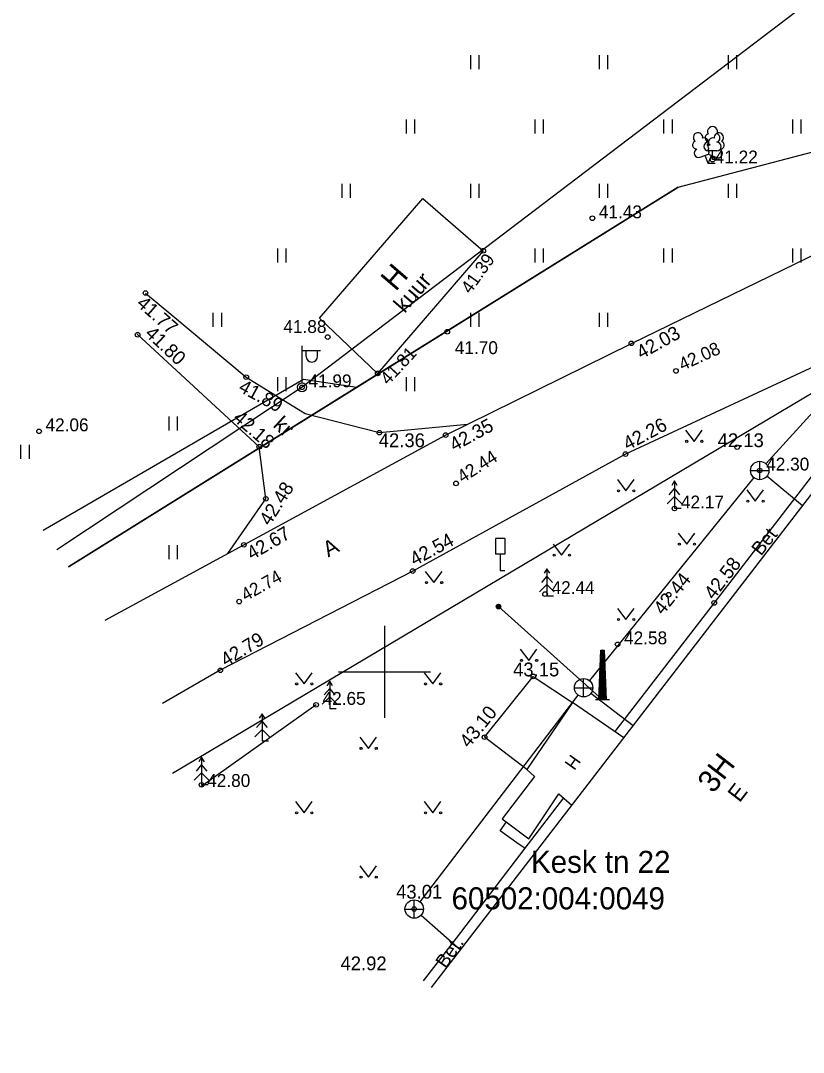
# Model space of a CAD drawing. Extents: x 641898 to 642452, y 6471715 to 6472255.
# Drawn here: x 641930.2 to 641972.8, y 6472029.3 to 6472085.4 of the extents above; entities that cross this region are included whole.
import ezdxf

# ---------------------------------------------------------------- set-up
doc = ezdxf.new("R2010")
doc.units = 0
for name, color, linetype in [('HALJASTUS', 7, 'Continuous'), ('HOONE', 7, 'Continuous'), ('HOONEDET', 7, 'Continuous'), ('KKAEV', 7, 'Continuous'), ('KORGUS-EH2000', 7, 'Continuous'), ('KTRASS', 7, 'Continuous'), ('LIIKLUS', 7, 'Continuous'), ('MPOHULIIN', 7, 'Continuous'), ('PIIR', 7, 'Continuous'), ('POST', 7, 'Continuous'), ('PUU', 7, 'Continuous'), ('RAJATIS', 7, 'Continuous'), ('TEE', 7, 'Continuous'), ('VORK', 7, 'Continuous')]:
    doc.layers.add(name, color=color, linetype=linetype)

msp = doc.modelspace()

# ---------------------------------------------------------------- linework, layer by layer
at = {"layer": 'HALJASTUS'}
for p, q in [((641954.672, 6472083.518), (641954.672, 6472082.757)), ((641955.127, 6472083.518), (641955.127, 6472082.757)), ((641961.672, 6472083.518), (641961.672, 6472082.757)), ((641962.127, 6472083.518), (641962.127, 6472082.757)), ((641968.672, 6472083.518), (641968.672, 6472082.757)), ((641969.127, 6472083.518), (641969.127, 6472082.757)), ((641951.172, 6472080.018), (641951.172, 6472079.257)), ((641951.627, 6472080.018), (641951.627, 6472079.257)), ((641958.172, 6472080.018), (641958.172, 6472079.257)), ((641958.627, 6472080.018), (641958.627, 6472079.257)), ((641965.172, 6472080.018), (641965.172, 6472079.257)), ((641965.627, 6472080.018), (641965.627, 6472079.257)), ((641972.172, 6472080.018), (641972.172, 6472079.257)), ((641972.627, 6472080.018), (641972.627, 6472079.257)), ((641947.672, 6472076.518), (641947.672, 6472075.757)), ((641948.127, 6472076.518), (641948.127, 6472075.757)), ((641954.672, 6472076.518), (641954.672, 6472075.757)), ((641955.127, 6472076.518), (641955.127, 6472075.757)), ((641961.672, 6472076.518), (641961.672, 6472075.757)), ((641962.127, 6472076.518), (641962.127, 6472075.757)), ((641968.672, 6472076.518), (641968.672, 6472075.757)), ((641969.127, 6472076.518), (641969.127, 6472075.757)), ((641944.172, 6472073.018), (641944.172, 6472072.257)), ((641944.627, 6472073.018), (641944.627, 6472072.257)), ((641958.172, 6472073.018), (641958.172, 6472072.257)), ((641958.627, 6472073.018), (641958.627, 6472072.257)), ((641965.172, 6472073.018), (641965.172, 6472072.257)), ((641965.627, 6472073.018), (641965.627, 6472072.257)), ((641972.172, 6472073.018), (641972.172, 6472072.257)), ((641972.627, 6472073.018), (641972.627, 6472072.257)), ((641940.672, 6472069.518), (641940.672, 6472068.757)), ((641941.127, 6472069.518), (641941.127, 6472068.757)), ((641954.672, 6472069.518), (641954.672, 6472068.757)), ((641955.127, 6472069.518), (641955.127, 6472068.757)), ((641961.672, 6472069.518), (641961.672, 6472068.757)), ((641962.127, 6472069.518), (641962.127, 6472068.757)), ((641944.172, 6472066.018), (641944.172, 6472065.257)), ((641944.627, 6472066.018), (641944.627, 6472065.257)), ((641951.172, 6472066.018), (641951.172, 6472065.257)), ((641951.627, 6472066.018), (641951.627, 6472065.257)), ((641938.272, 6472063.881), (641938.272, 6472063.119)), ((641938.728, 6472063.881), (641938.728, 6472063.119)), ((641966.362, 6472063.136), (641966.826, 6472062.529)), ((641966.826, 6472062.529), (641967.271, 6472063.136)), ((641930.214, 6472062.337), (641930.214, 6472061.576)), ((641930.669, 6472062.337), (641930.669, 6472061.576)), ((641962.658, 6472060.448), (641963.121, 6472059.841)), ((641963.121, 6472059.841), (641963.567, 6472060.448)), ((641969.69, 6472059.885), (641970.154, 6472059.278)), ((641970.154, 6472059.278), (641970.599, 6472059.885)), ((641965.962, 6472057.545), (641966.426, 6472056.939)), ((641966.426, 6472056.939), (641966.871, 6472057.545)), ((641938.272, 6472056.881), (641938.272, 6472056.119)), ((641938.728, 6472056.881), (641938.728, 6472056.119)), ((641959.158, 6472056.948), (641959.621, 6472056.341)), ((641959.621, 6472056.341), (641960.067, 6472056.948)), ((641952.214, 6472055.455), (641952.677, 6472054.848)), ((641952.677, 6472054.848), (641953.123, 6472055.455)), ((641962.658, 6472053.448), (641963.121, 6472052.841)), ((641963.121, 6472052.841), (641963.567, 6472053.448)), ((641957.377, 6472051.23), (641957.841, 6472050.624)), ((641957.841, 6472050.624), (641958.286, 6472051.23)), ((641945.158, 6472049.948), (641945.621, 6472049.341)), ((641945.621, 6472049.341), (641946.067, 6472049.948)), ((641952.158, 6472049.948), (641952.621, 6472049.341)), ((641952.621, 6472049.341), (641953.067, 6472049.948)), ((641948.658, 6472046.448), (641949.121, 6472045.841)), ((641949.121, 6472045.841), (641949.567, 6472046.448)), ((641945.158, 6472042.948), (641945.621, 6472042.341)), ((641945.621, 6472042.341), (641946.067, 6472042.948)), ((641952.158, 6472042.948), (641952.621, 6472042.341)), ((641952.621, 6472042.341), (641953.067, 6472042.948)), ((641948.658, 6472039.448), (641949.121, 6472038.841)), ((641949.121, 6472038.841), (641949.567, 6472039.448))]:
    msp.add_line(p, q, dxfattribs=at)
msp.add_lwpolyline([(641946.278, 6472048.205), (641940.006, 6472043.742)], dxfattribs=at)
for centre in [(641966.425, 6472062.529), (641967.253, 6472062.529), (641962.72, 6472059.841), (641963.549, 6472059.841), (641969.752, 6472059.278), (641970.581, 6472059.278), (641966.025, 6472056.939), (641966.853, 6472056.939), (641959.22, 6472056.341), (641960.049, 6472056.341), (641952.276, 6472054.848), (641953.105, 6472054.848), (641962.72, 6472052.841), (641963.549, 6472052.841), (641957.44, 6472050.624), (641958.268, 6472050.624), (641945.22, 6472049.341), (641946.049, 6472049.341), (641952.22, 6472049.341), (641953.049, 6472049.341), (641948.72, 6472045.841), (641949.549, 6472045.841), (641945.22, 6472042.341), (641946.049, 6472042.341), (641952.22, 6472042.341), (641953.049, 6472042.341), (641948.72, 6472038.841), (641949.549, 6472038.841)]:
    msp.add_circle(centre, 0.055, dxfattribs=at)
at = {"layer": 'HOONE'}
for points in [[(641955.368, 6472072.89), (641949.623, 6472066.223), (641946.465, 6472069.219), (641952.074, 6472075.728), (641955.368, 6472072.89)], [(641952.546, 6472032.842), (641977.787, 6472065.6), (641985.309, 6472059.834)], [(641963.009, 6472046.42), (641960.211, 6472048.337), (641957.726, 6472044.694), (641958.152, 6472044.31), (641956.393, 6472042.014), (641957.846, 6472040.928), (641959.482, 6472043.364), (641960.186, 6472042.745)]]:
    msp.add_lwpolyline(points, dxfattribs=at)
at = {"layer": 'HOONEDET'}
for points in [[(641985.65, 6472060.289), (641982.679, 6472062.575), (641977.685, 6472066.396), (641973.2, 6472060.604), (641967.921, 6472053.748), (641962.509, 6472046.762)], [(641957.726, 6472044.694), (641955.438, 6472046.449), (641958.086, 6472049.753), (641960.211, 6472048.337), (641957.726, 6472044.694)], [(641959.728, 6472043.148), (641957.622, 6472040.414), (641953.596, 6472035.143), (641952.1, 6472033.2)], [(641957.622, 6472040.414), (641957.321, 6472040.616), (641956.277, 6472041.352), (641956.63, 6472041.843)]]:
    msp.add_lwpolyline(points, dxfattribs=at)
at = {"layer": 'KKAEV'}
for p, q in [((641970.395, 6472060.443), (641970.395, 6472061.443)), ((641969.895, 6472060.943), (641970.895, 6472060.943)), ((641960.819, 6472048.634), (641960.819, 6472049.634)), ((641960.319, 6472049.134), (641961.319, 6472049.134)), ((641951.61, 6472036.606), (641951.61, 6472037.606)), ((641951.11, 6472037.106), (641952.11, 6472037.106))]:
    msp.add_line(p, q, dxfattribs=at)
for centre in [(641970.395, 6472060.943), (641960.819, 6472049.134), (641951.61, 6472037.106)]:
    msp.add_circle(centre, 0.5, dxfattribs=at)
at = {"layer": 'KORGUS-EH2000'}
for centre in [(641967.83, 6472077.843), (641961.299, 6472074.654), (641955.368, 6472072.89), (641937, 6472070.591), (641953.409, 6472068.486), (641936.572, 6472068.325), (641946.909, 6472068.199), (641963.417, 6472067.855), (641965.841, 6472066.356), (641942.478, 6472066.02), (641949.623, 6472066.223), (641945.513, 6472065.466), (641931.216, 6472063.075), (641949.719, 6472063.001), (641953.32, 6472062.868), (641943.188, 6472062.236), (641963.095, 6472061.835), (641969.169, 6472062.213), (641970.395, 6472060.943), (641953.885, 6472060.242), (641943.545, 6472059.406), (641965.759, 6472058.88), (641942.346, 6472056.906), (641951.531, 6472055.479), (641958.726, 6472054.227), (641965.442, 6472054.192), (641942.097, 6472053.819), (641967.921, 6472053.748), (641962.669, 6472051.496), (641941.069, 6472050.083), (641958.086, 6472049.753), (641946.278, 6472048.205), (641955.438, 6472046.449), (641940.051, 6472043.856), (641951.61, 6472037.106)]:
    msp.add_circle(centre, 0.125, dxfattribs=at)
at = {"layer": 'KTRASS'}
for points in [[(641975.895, 6472066.969), (641970.73, 6472061.314)], [(641970.079, 6472060.556), (641961.134, 6472049.522)], [(641972.719, 6472059.023), (641970.786, 6472060.631)], [(641960.515, 6472048.737), (641951.914, 6472037.503)], [(641963.506, 6472047.065), (641961.215, 6472048.829)], [(641951.986, 6472036.776), (641954.128, 6472034.895)]]:
    msp.add_lwpolyline(points, dxfattribs=at)
at = {"layer": 'LIIKLUS'}
for points in [[(641956.035, 6472057.242), (641956.035, 6472056.392)], [(641956.535, 6472057.242), (641956.035, 6472057.242)], [(641956.535, 6472057.242), (641956.535, 6472056.392)], [(641956.535, 6472056.392), (641956.035, 6472056.392)], [(641956.285, 6472056.392), (641956.285, 6472055.492)], [(641956.535, 6472055.492), (641956.285, 6472055.492)]]:
    msp.add_lwpolyline(points, dxfattribs=at)
at = {"layer": 'MPOHULIIN'}
msp.add_lwpolyline([(642355.522, 6471813.313), (642331.534, 6471832.393), (642302.222, 6471855.921), (642271.629, 6471880.301), (642234.793, 6471909.555), (642198.436, 6471939.015), (642169.975, 6471961.956), (642133.076, 6471995.171), (642102.99, 6472021.089), (642074.552, 6472045.947), (642044.597, 6472041.824), (642019.939, 6472060.923), (641980.015, 6472091.706), (641945.513, 6472065.466), (641932.178, 6472056.628)], dxfattribs=at)
at = {"layer": 'PIIR'}
for p, q in [((641965.96, 6472076.34), (641988.23, 6472082.2)), ((641932.814, 6472055.705), (641965.96, 6472076.34)), ((641965.96, 6472076.34), (641948.49, 6472065.47)), ((641938.475, 6472044.5), (641978.1, 6472068.06)), ((641931.443, 6472057.695), (641945.59, 6472065.91)), ((641945.59, 6472065.91), (641948.49, 6472065.47)), ((641948.49, 6472065.47), (641932.812, 6472055.707))]:
    msp.add_line(p, q, dxfattribs=at)
at = {"layer": 'POST'}
for p, q in [((641945.513, 6472065.716), (641945.513, 6472067.716)), ((641945.513, 6472067.466), (641946.513, 6472067.466)), ((641945.74, 6472067.145), (641945.74, 6472067.466)), ((641946.352, 6472067.145), (641946.352, 6472067.466))]:
    msp.add_line(p, q, dxfattribs=at)
msp.add_circle((641945.513, 6472065.466), 0.25, dxfattribs=at)
msp.add_arc((641946.046, 6472067.145), 0.306, 180, 0, dxfattribs=at)
at = {"layer": 'PUU'}
for p, q in [((641967.157, 6472077.97), (641967.602, 6472078.145)), ((641968.07, 6472078.318), (641967.59, 6472078.318)), ((641967.602, 6472078.145), (641968.042, 6472077.965)), ((641967.83, 6472077.843), (641967.83, 6472078.318)), ((641967.597, 6472077.635), (641967.422, 6472078.075)), ((641967.597, 6472077.635), (641967.777, 6472078.075)), ((641967.977, 6472077.635), (641967.597, 6472077.635)), ((641968.21, 6472077.843), (641967.83, 6472077.843)), ((641965.759, 6472060.38), (641965.609, 6472060.13)), ((641965.909, 6472060.13), (641965.759, 6472060.38)), ((641965.759, 6472060.38), (641965.759, 6472058.88)), ((641965.759, 6472059.98), (641965.459, 6472059.63)), ((641966.059, 6472059.63), (641965.759, 6472059.98)), ((641965.759, 6472059.53), (641965.359, 6472059.13)), ((641966.159, 6472059.13), (641965.759, 6472059.53)), ((641966.119, 6472058.88), (641965.759, 6472058.88)), ((641958.827, 6472055.206), (641958.527, 6472054.856)), ((641958.827, 6472055.606), (641958.677, 6472055.356)), ((641958.977, 6472055.356), (641958.827, 6472055.606)), ((641958.827, 6472055.606), (641958.827, 6472054.106)), ((641959.127, 6472054.856), (641958.827, 6472055.206)), ((641958.827, 6472054.756), (641958.427, 6472054.356)), ((641959.227, 6472054.356), (641958.827, 6472054.756)), ((641959.187, 6472054.106), (641958.827, 6472054.106)), ((641947.015, 6472049.092), (641946.715, 6472048.742)), ((641947.015, 6472049.492), (641946.865, 6472049.242)), ((641947.165, 6472049.242), (641947.015, 6472049.492)), ((641947.015, 6472049.492), (641947.015, 6472047.992)), ((641947.315, 6472048.742), (641947.015, 6472049.092)), ((641947.015, 6472048.642), (641946.615, 6472048.242)), ((641947.415, 6472048.242), (641947.015, 6472048.642)), ((641947.375, 6472047.992), (641947.015, 6472047.992)), ((641943.338, 6472047.323), (641943.038, 6472046.973)), ((641943.338, 6472047.723), (641943.188, 6472047.473)), ((641943.488, 6472047.473), (641943.338, 6472047.723)), ((641943.338, 6472047.723), (641943.338, 6472046.223)), ((641943.638, 6472046.973), (641943.338, 6472047.323)), ((641943.338, 6472046.873), (641942.938, 6472046.473)), ((641943.738, 6472046.473), (641943.338, 6472046.873)), ((641943.698, 6472046.223), (641943.338, 6472046.223)), ((641940.051, 6472045.356), (641939.901, 6472045.106)), ((641940.201, 6472045.106), (641940.051, 6472045.356)), ((641940.051, 6472045.356), (641940.051, 6472043.856)), ((641940.051, 6472044.506), (641939.651, 6472044.106)), ((641940.051, 6472044.956), (641939.751, 6472044.606)), ((641940.351, 6472044.606), (641940.051, 6472044.956)), ((641940.451, 6472044.106), (641940.051, 6472044.506)), ((641940.411, 6472043.856), (641940.051, 6472043.856))]:
    msp.add_line(p, q, dxfattribs=at)
msp.add_lwpolyline([(641967.602, 6472078.64), (641967.582, 6472078.565), (641967.582, 6472078.545), (641967.592, 6472078.515), (641967.612, 6472078.48), (641967.617, 6472078.46), (641967.602, 6472078.425), (641967.577, 6472078.375), (641967.572, 6472078.35), (641967.577, 6472078.335), (641967.587, 6472078.305), (641967.622, 6472078.245), (641967.627, 6472078.225), (641967.622, 6472078.205), (641967.607, 6472078.17), (641967.602, 6472078.145)], dxfattribs=at)
for centre, radius, start, end in [((641967.04, 6472079.049), 0.256, 111.5027, 232.5173), ((641967.04, 6472079.049), 0.256, 350.4856, 111.5002), ((641967.83, 6472079.363), 0.277, 332.5799, 207.4201), ((641968.176, 6472079.04), 0.256, 67.6168, 188.6314), ((641968.176, 6472079.04), 0.256, 306.5997, 67.6143), ((641966.966, 6472078.638), 0.224, 111.4304, 274.4987), ((641967.375, 6472078.799), 0.224, 308.5041, 111.5725), ((641967.593, 6472078.555), 0.238, 90.0016, 269.3953), ((641967.66, 6472079.016), 0.233, 109.0217, 253.1415), ((641967.838, 6472078.794), 0.225, 67.7016, 230.5126), ((641968, 6472079.016), 0.233, 286.8508, 70.9859), ((641968.067, 6472078.555), 0.238, 270.6047, 89.9984), ((641968.243, 6472078.628), 0.224, 264.6183, 67.6866), ((641967.071, 6472078.193), 0.237, 111.5014, 291.5004), ((641967.601, 6472078.402), 0.237, 66.7655, 111.5015), ((641968.132, 6472078.185), 0.237, 247.6166, 67.6155)]:
    msp.add_arc(centre, radius, start, end, dxfattribs=at)
at = {"layer": 'RAJATIS'}
for p, q in [((641961.655, 6472048.486), (641961.751, 6472051.181)), ((641961.97, 6472050.451), (641961.733, 6472050.676)), ((641961.967, 6472050.523), (641961.736, 6472050.742)), ((641961.965, 6472050.594), (641961.738, 6472050.809)), ((641961.962, 6472050.665), (641961.741, 6472050.876)), ((641961.96, 6472050.737), (641961.743, 6472050.942)), ((641961.957, 6472050.808), (641961.745, 6472051.009)), ((641961.955, 6472050.879), (641961.748, 6472051.076)), ((641961.952, 6472050.951), (641961.75, 6472051.142)), ((641961.751, 6472051.181), (641961.944, 6472051.181)), ((641961.95, 6472051.022), (641961.782, 6472051.181)), ((641961.947, 6472051.093), (641961.855, 6472051.181)), ((641961.945, 6472051.165), (641961.928, 6472051.181)), ((641961.944, 6472051.181), (641962.04, 6472048.486)), ((641961.99, 6472049.881), (641961.714, 6472050.143)), ((641961.988, 6472049.952), (641961.717, 6472050.209)), ((641961.985, 6472050.023), (641961.719, 6472050.276)), ((641961.983, 6472050.095), (641961.722, 6472050.342)), ((641961.98, 6472050.166), (641961.724, 6472050.409)), ((641961.978, 6472050.237), (641961.726, 6472050.476)), ((641961.975, 6472050.309), (641961.729, 6472050.542)), ((641961.973, 6472050.38), (641961.731, 6472050.609)), ((641962.013, 6472049.239), (641961.693, 6472049.543)), ((641962.011, 6472049.31), (641961.695, 6472049.609)), ((641962.008, 6472049.381), (641961.698, 6472049.676)), ((641962.006, 6472049.453), (641961.7, 6472049.743)), ((641962.003, 6472049.524), (641961.702, 6472049.809)), ((641962.001, 6472049.595), (641961.705, 6472049.876)), ((641961.998, 6472049.667), (641961.707, 6472049.943)), ((641961.996, 6472049.738), (641961.71, 6472050.009)), ((641961.993, 6472049.809), (641961.712, 6472050.076)), ((641962.034, 6472048.668), (641961.674, 6472049.009)), ((641962.031, 6472048.739), (641961.676, 6472049.077)), ((641962.029, 6472048.811), (641961.679, 6472049.143)), ((641962.026, 6472048.882), (641961.681, 6472049.209)), ((641962.024, 6472048.953), (641961.683, 6472049.276)), ((641962.021, 6472049.025), (641961.686, 6472049.343)), ((641962.018, 6472049.096), (641961.688, 6472049.409)), ((641962.016, 6472049.167), (641961.691, 6472049.476)), ((641962.233, 6472048.486), (641961.463, 6472048.486)), ((641962.04, 6472048.486), (641961.655, 6472048.486)), ((641961.717, 6472048.486), (641961.657, 6472048.543)), ((641961.79, 6472048.486), (641961.66, 6472048.609)), ((641961.863, 6472048.486), (641961.662, 6472048.676)), ((641961.935, 6472048.486), (641961.664, 6472048.743)), ((641962.008, 6472048.486), (641961.667, 6472048.809)), ((641962.039, 6472048.525), (641961.669, 6472048.876)), ((641962.036, 6472048.597), (641961.672, 6472048.943))]:
    msp.add_line(p, q, dxfattribs=at)
msp.add_lwpolyline([(641961.848, 6472048.486), (641956.194, 6472053.546)], dxfattribs=at)
for radius in [0.125, 0.117, 0.109, 0.102, 0.0938, 0.086, 0.0782, 0.0704, 0.0626, 0.0548, 0.047, 0.0392, 0.0314, 0.0236, 0.0158, 0.00798, 0.000186]:
    msp.add_circle((641956.194, 6472053.546), radius, dxfattribs=at)
at = {"layer": 'TEE'}
for points in [[(641934.805, 6472052.814), (641942.346, 6472056.906), (641953.32, 6472062.868), (641963.417, 6472067.855), (641974.376, 6472073.181), (641981.442, 6472075.609), (641990.636, 6472078.487), (642002.72, 6472078.372)], [(642000.586, 6472072.315), (641991.524, 6472072.15), (641983.244, 6472070.143), (641974.639, 6472067.194), (641963.095, 6472061.835), (641951.531, 6472055.479), (641941.069, 6472050.083), (641937.926, 6472048.284)], [(641937, 6472070.591), (641938.371, 6472069.447), (641942.478, 6472066.02), (641945.683, 6472064.046), (641949.719, 6472063.001), (641954.513, 6472063.457)], [(641941.482, 6472056.437), (641943.545, 6472059.406), (641943.188, 6472062.236), (641936.545, 6472068.35)]]:
    msp.add_lwpolyline(points, dxfattribs=at)
at = {"layer": 'VORK'}
for p, q in [((641950, 6472052.5), (641950, 6472047.5)), ((641947.5, 6472050), (641952.5, 6472050))]:
    msp.add_line(p, q, dxfattribs=at)

# ---------------------------------------------------------------- texts
at = {"layer": 'HOONE'}
for s, height, rotation, p in [('H', 1.2, 49.2483, (641950.601, 6472070.637)), ('kuur', 0.9, 49.2483, (641951.093, 6472069.456)), ('H', 0.7, 234.6571, (641960.14, 6472045.558)), ('3H', 1.2, 52.4257, (641967.87, 6472043.341)), ('E', 0.9, 52.4257, (641969.296, 6472042.853))]:
    msp.add_text(s, height=height, rotation=rotation, dxfattribs=at).set_placement(p)
at = {"layer": 'HOONEDET'}
for s, rotation, p in [('Bet', 51.8283, (641970.467, 6472056.264)), ('Bet.', 55.191, (641953.33, 6472033.828))]:
    msp.add_text(s, height=0.75, rotation=rotation, dxfattribs=at).set_placement(p)
at = {"layer": 'KORGUS-EH2000'}
for s, height, p in [('41.22', 0.7, (641967.947, 6472077.635)), ('41.43', 0.7, (641961.649, 6472074.654)), ('41.88', 0.7, (641944.499, 6472068.419)), ('41.70', 0.7, (641953.818, 6472067.271)), ('41.99', 0.7, (641945.863, 6472065.466)), ('42.06', 0.7, (641931.566, 6472063.075)), ('42.36', 0.75, (641949.683, 6472062.212)), ('42.13', 0.75, (641968.106, 6472062.213)), ('42.30', 0.7, (641970.745, 6472060.943)), ('42.17', 0.7, (641966.109, 6472058.88)), ('42.44', 0.7, (641959.076, 6472054.227)), ('42.58', 0.7, (641963.019, 6472051.496)), ('43.15', 0.75, (641956.988, 6472049.753)), ('42.65', 0.7, (641946.628, 6472048.205)), ('42.80', 0.7, (641940.356, 6472043.742)), ('43.01', 0.75, (641950.626, 6472037.673)), ('42.92', 0.75, (641947.603, 6472033.777))]:
    msp.add_text(s, height=height, dxfattribs=at).set_placement(p)
for s, height, rotation, p in [('41.39', 0.7, 54.441, (641954.661, 6472070.506)), ('41.77', 0.75, 318.5277, (641936.467, 6472069.946)), ('41.80', 0.75, 316.9828, (641936.922, 6472068.325)), ('42.03', 0.75, 28.9992, (641963.956, 6472066.973)), ('41.81', 0.7, 47.0581, (641950.198, 6472065.554)), ('42.08', 0.7, 24.4206, (641966.191, 6472066.356)), ('41.89', 0.75, 331.324, (641942.003, 6472065.281)), ('42.18', 0.75, 319.0274, (641941.709, 6472063.713)), ('42.35', 0.75, 28.4493, (641953.787, 6472061.961)), ('42.26', 0.75, 27.8962, (641963.215, 6472062.017)), ('42.44', 0.7, 32.5507, (641954.235, 6472060.242)), ('42.48', 0.75, 57.7082, (641943.761, 6472057.895)), ('42.67', 0.75, 29.9845, (641942.78, 6472056.05)), ('42.54', 0.75, 28.2033, (641951.628, 6472055.738)), ('42.58', 0.75, 52.5381, (641967.896, 6472053.872)), ('42.74', 0.7, 29.2857, (641942.447, 6472053.819)), ('42.44', 0.75, 51.3221, (641965.133, 6472053.045)), ('42.79', 0.75, 30.9447, (641941.369, 6472050.263)), ('43.10', 0.75, 51.3198, (641954.587, 6472045.814))]:
    msp.add_text(s, height=height, rotation=rotation, dxfattribs=at).set_placement(p)
at = {"layer": 'PIIR'}
for s, p in [('Kesk tn 22', (641957.96, 6472039.071)), ('60502:004:0049', (641953.64, 6472037.087))]:
    msp.add_text(s, height=1.2, dxfattribs=at).set_placement(p)
at = {"layer": 'TEE'}
for s, rotation, p in [('kr', 317.3753, (641943.888, 6472063.35)), ('A', 28.4888, (641946.936, 6472056.21))]:
    msp.add_text(s, height=0.85, rotation=rotation, dxfattribs=at).set_placement(p)

doc.saveas('drawing.dxf')
